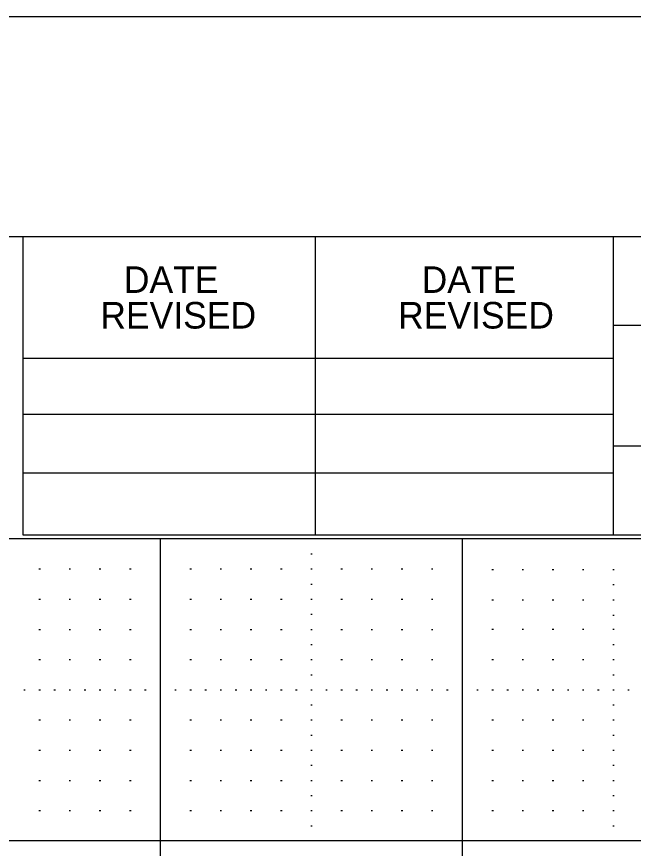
# Model space of a CAD drawing. Extents: x 0 to 34, y 0 to 22.
# Drawn here: x 26.93 to 28.972, y 19.247 to 22 of the extents above; entities that cross this region are included whole.
import ezdxf

# ---------------------------------------------------------------- set-up
doc = ezdxf.new("R2010")
doc.units = 0
for name, color, linetype in [('Level 1', 7, 'Continuous'), ('Level 4', 7, 'Continuous'), ('Level 5', 7, 'Continuous'), ('Level 63', 7, 'Continuous')]:
    doc.layers.add(name, color=color, linetype=linetype)

msp = doc.modelspace()

# ---------------------------------------------------------------- linework, layer by layer
at = {"layer": 'Level 1'}
for p, q in [((1.597, 21.272), (33.215, 21.272)), ((26.951, 20.2839), (26.951, 21.2719)), ((27.919, 20.2839), (27.919, 21.272)), ((28.905, 21.2719), (28.905, 20.2839)), ((33.215, 20.9779), (28.905, 20.9779)), ((26.951, 20.8699), (28.905, 20.8699)), ((26.951, 20.6839), (28.905, 20.6839)), ((33.215, 20.5779), (28.905, 20.5779)), ((26.951, 20.4899), (28.905, 20.4899)), ((33.215, 20.2839), (26.951, 20.2839))]:
    msp.add_line(p, q, dxfattribs=at)
at = {"layer": 'Level 4'}
for p, q in [((33.215, 20.272), (1.597, 20.272)), ((27.406, 1.272), (27.406, 20.272)), ((28.406, 1.272), (28.406, 20.272)), ((33.215, 19.272), (1.597, 19.272))]:
    msp.add_line(p, q, dxfattribs=at)
at = {"layer": 'Level 5'}
for p, q in [((27.9035, 20.2219), (27.9085, 20.2219)), ((27.0035, 20.1719), (27.0085, 20.1719)), ((27.1035, 20.1719), (27.1085, 20.1719)), ((27.2035, 20.1719), (27.2085, 20.1719)), ((27.3035, 20.1719), (27.3085, 20.1719)), ((27.5035, 20.1719), (27.5085, 20.1719)), ((27.6035, 20.1719), (27.6085, 20.1719)), ((27.7035, 20.1719), (27.7085, 20.1719)), ((27.8035, 20.1719), (27.8085, 20.1719)), ((27.9035, 20.1719), (27.9085, 20.1719)), ((28.0035, 20.1719), (28.0085, 20.1719)), ((28.1035, 20.1719), (28.1085, 20.1719)), ((28.2035, 20.1719), (28.2085, 20.1719)), ((28.3035, 20.1719), (28.3085, 20.1719)), ((28.5035, 20.1705), (28.5085, 20.1705)), ((28.6035, 20.1705), (28.6085, 20.1705)), ((28.7035, 20.1705), (28.7085, 20.1705)), ((28.8035, 20.1705), (28.8085, 20.1705)), ((28.9035, 20.1705), (28.9085, 20.1705)), ((27.9035, 20.1219), (27.9085, 20.1219)), ((28.9035, 20.1205), (28.9085, 20.1205)), ((27.0035, 20.0719), (27.0085, 20.0719)), ((27.1035, 20.0719), (27.1085, 20.0719)), ((27.2035, 20.0719), (27.2085, 20.0719)), ((27.3035, 20.0719), (27.3085, 20.0719)), ((27.5035, 20.0719), (27.5085, 20.0719)), ((27.6035, 20.0719), (27.6085, 20.0719)), ((27.7035, 20.0719), (27.7085, 20.0719)), ((27.8035, 20.0719), (27.8085, 20.0719)), ((27.9035, 20.0719), (27.9085, 20.0719)), ((28.0035, 20.0719), (28.0085, 20.0719)), ((28.1035, 20.0719), (28.1085, 20.0719)), ((28.2035, 20.0719), (28.2085, 20.0719)), ((28.3035, 20.0719), (28.3085, 20.0719)), ((28.5035, 20.0691), (28.5085, 20.0691)), ((28.6035, 20.0691), (28.6085, 20.0691)), ((28.7035, 20.0691), (28.7085, 20.0691)), ((28.8035, 20.0691), (28.8085, 20.0691)), ((28.9035, 20.0691), (28.9085, 20.0691)), ((27.9035, 20.0219), (27.9085, 20.0219)), ((28.9035, 20.0191), (28.9085, 20.0191)), ((27.0035, 19.9719), (27.0085, 19.9719)), ((27.1035, 19.9719), (27.1085, 19.9719)), ((27.2035, 19.9719), (27.2085, 19.9719)), ((27.3035, 19.9719), (27.3085, 19.9719)), ((27.5035, 19.9719), (27.5085, 19.9719)), ((27.6035, 19.9719), (27.6085, 19.9719)), ((27.7035, 19.9719), (27.7085, 19.9719)), ((27.8035, 19.9719), (27.8085, 19.9719)), ((27.9035, 19.9719), (27.9085, 19.9719)), ((28.0035, 19.9719), (28.0085, 19.9719)), ((28.1035, 19.9719), (28.1085, 19.9719)), ((28.2035, 19.9719), (28.2085, 19.9719)), ((28.3035, 19.9719), (28.3085, 19.9719)), ((28.5035, 19.9722), (28.5085, 19.9722)), ((28.6035, 19.9722), (28.6085, 19.9722)), ((28.7035, 19.9722), (28.7085, 19.9722)), ((28.8035, 19.9722), (28.8085, 19.9722)), ((28.9035, 19.9722), (28.9085, 19.9722)), ((27.9035, 19.9219), (27.9085, 19.9219)), ((28.9035, 19.9222), (28.9085, 19.9222)), ((27.0035, 19.8719), (27.0085, 19.8719)), ((27.1035, 19.8719), (27.1085, 19.8719)), ((27.2035, 19.8719), (27.2085, 19.8719)), ((27.3035, 19.8719), (27.3085, 19.8719)), ((27.5035, 19.8719), (27.5085, 19.8719)), ((27.6035, 19.8719), (27.6085, 19.8719)), ((27.7035, 19.8719), (27.7085, 19.8719)), ((27.8035, 19.8719), (27.8085, 19.8719)), ((27.9035, 19.8719), (27.9085, 19.8719)), ((28.0035, 19.8719), (28.0085, 19.8719)), ((28.1035, 19.8719), (28.1085, 19.8719)), ((28.2035, 19.8719), (28.2085, 19.8719)), ((28.3035, 19.8719), (28.3085, 19.8719)), ((28.5035, 19.8719), (28.5085, 19.8719)), ((28.6035, 19.8719), (28.6085, 19.8719)), ((28.7035, 19.8719), (28.7085, 19.8719)), ((28.8035, 19.8719), (28.8085, 19.8719)), ((28.9035, 19.8719), (28.9085, 19.8719)), ((27.9035, 19.8219), (27.9085, 19.8219)), ((28.9035, 19.8219), (28.9085, 19.8219)), ((26.9535, 19.7719), (26.9585, 19.7719)), ((27.0035, 19.7719), (27.0085, 19.7719)), ((27.0535, 19.7719), (27.0585, 19.7719)), ((27.1035, 19.7719), (27.1085, 19.7719)), ((27.1535, 19.7719), (27.1585, 19.7719)), ((27.2035, 19.7719), (27.2085, 19.7719)), ((27.2535, 19.7719), (27.2585, 19.7719)), ((27.3035, 19.7719), (27.3085, 19.7719)), ((27.3535, 19.7719), (27.3585, 19.7719)), ((27.4535, 19.7719), (27.4585, 19.7719)), ((27.5035, 19.7719), (27.5085, 19.7719)), ((27.5535, 19.7719), (27.5585, 19.7719)), ((27.6035, 19.7719), (27.6085, 19.7719)), ((27.6535, 19.7719), (27.6585, 19.7719)), ((27.7035, 19.7719), (27.7085, 19.7719)), ((27.7535, 19.7719), (27.7585, 19.7719)), ((27.8035, 19.7719), (27.8085, 19.7719)), ((27.8535, 19.7719), (27.8585, 19.7719)), ((27.9035, 19.7719), (27.9085, 19.7719)), ((27.9535, 19.7719), (27.9585, 19.7719)), ((28.0035, 19.7719), (28.0085, 19.7719)), ((28.0535, 19.7719), (28.0585, 19.7719)), ((28.1035, 19.7719), (28.1085, 19.7719)), ((28.1535, 19.7719), (28.1585, 19.7719)), ((28.2035, 19.7719), (28.2085, 19.7719)), ((28.2535, 19.7719), (28.2585, 19.7719)), ((28.3035, 19.7719), (28.3085, 19.7719)), ((28.3535, 19.7719), (28.3585, 19.7719)), ((28.4535, 19.7719), (28.4585, 19.7719)), ((28.5035, 19.7719), (28.5085, 19.7719)), ((28.5535, 19.7719), (28.5585, 19.7719)), ((28.6035, 19.7719), (28.6085, 19.7719)), ((28.6535, 19.7719), (28.6585, 19.7719)), ((28.7035, 19.7719), (28.7085, 19.7719)), ((28.7535, 19.7719), (28.7585, 19.7719)), ((28.8035, 19.7719), (28.8085, 19.7719)), ((28.8535, 19.7719), (28.8585, 19.7719)), ((28.9035, 19.7719), (28.9085, 19.7719)), ((28.9535, 19.7719), (28.9585, 19.7719)), ((27.9035, 19.7219), (27.9085, 19.7219)), ((28.9035, 19.7219), (28.9085, 19.7219)), ((27.0035, 19.6719), (27.0085, 19.6719)), ((27.1035, 19.6719), (27.1085, 19.6719)), ((27.2035, 19.6719), (27.2085, 19.6719)), ((27.3035, 19.6719), (27.3085, 19.6719)), ((27.5035, 19.6719), (27.5085, 19.6719)), ((27.6035, 19.6719), (27.6085, 19.6719)), ((27.7035, 19.6719), (27.7085, 19.6719)), ((27.8035, 19.6719), (27.8085, 19.6719)), ((27.9035, 19.6719), (27.9085, 19.6719)), ((28.0035, 19.6719), (28.0085, 19.6719)), ((28.1035, 19.6719), (28.1085, 19.6719)), ((28.2035, 19.6719), (28.2085, 19.6719)), ((28.3035, 19.6719), (28.3085, 19.6719)), ((28.5035, 19.6719), (28.5085, 19.6719)), ((28.6035, 19.6719), (28.6085, 19.6719)), ((28.7035, 19.6719), (28.7085, 19.6719)), ((28.8035, 19.6719), (28.8085, 19.6719)), ((28.9035, 19.6719), (28.9085, 19.6719)), ((27.9035, 19.6219), (27.9085, 19.6219)), ((28.9035, 19.6219), (28.9085, 19.6219)), ((27.0035, 19.5719), (27.0085, 19.5719)), ((27.1035, 19.5719), (27.1085, 19.5719)), ((27.2035, 19.5719), (27.2085, 19.5719)), ((27.3035, 19.5719), (27.3085, 19.5719)), ((27.5035, 19.5719), (27.5085, 19.5719)), ((27.6035, 19.5719), (27.6085, 19.5719)), ((27.7035, 19.5719), (27.7085, 19.5719)), ((27.8035, 19.5719), (27.8085, 19.5719)), ((27.9035, 19.5719), (27.9085, 19.5719)), ((28.0035, 19.5719), (28.0085, 19.5719)), ((28.1035, 19.5719), (28.1085, 19.5719)), ((28.2035, 19.5719), (28.2085, 19.5719)), ((28.3035, 19.5719), (28.3085, 19.5719)), ((28.5035, 19.5719), (28.5085, 19.5719)), ((28.6035, 19.5719), (28.6085, 19.5719)), ((28.7035, 19.5719), (28.7085, 19.5719)), ((28.8035, 19.5719), (28.8085, 19.5719)), ((28.9035, 19.5719), (28.9085, 19.5719)), ((27.9035, 19.5219), (27.9085, 19.5219)), ((28.9035, 19.5219), (28.9085, 19.5219)), ((27.0035, 19.4719), (27.0085, 19.4719)), ((27.1035, 19.4719), (27.1085, 19.4719)), ((27.2035, 19.4719), (27.2085, 19.4719)), ((27.3035, 19.4719), (27.3085, 19.4719)), ((27.5035, 19.4719), (27.5085, 19.4719)), ((27.6035, 19.4719), (27.6085, 19.4719)), ((27.7035, 19.4719), (27.7085, 19.4719)), ((27.8035, 19.4719), (27.8085, 19.4719)), ((27.9035, 19.4719), (27.9085, 19.4719)), ((28.0035, 19.4719), (28.0085, 19.4719)), ((28.1035, 19.4719), (28.1085, 19.4719)), ((28.2035, 19.4719), (28.2085, 19.4719)), ((28.3035, 19.4719), (28.3085, 19.4719)), ((28.5035, 19.4719), (28.5085, 19.4719)), ((28.6035, 19.4719), (28.6085, 19.4719)), ((28.7035, 19.4719), (28.7085, 19.4719)), ((28.8035, 19.4719), (28.8085, 19.4719)), ((28.9035, 19.4719), (28.9085, 19.4719)), ((27.9035, 19.4219), (27.9085, 19.4219)), ((28.9035, 19.4219), (28.9085, 19.4219)), ((27.0035, 19.3719), (27.0085, 19.3719)), ((27.1035, 19.3719), (27.1085, 19.3719)), ((27.2035, 19.3719), (27.2085, 19.3719)), ((27.3035, 19.3719), (27.3085, 19.3719)), ((27.5035, 19.3719), (27.5085, 19.3719)), ((27.6035, 19.3719), (27.6085, 19.3719)), ((27.7035, 19.3719), (27.7085, 19.3719)), ((27.8035, 19.3719), (27.8085, 19.3719)), ((27.9035, 19.3719), (27.9085, 19.3719)), ((28.0035, 19.3719), (28.0085, 19.3719)), ((28.1035, 19.3719), (28.1085, 19.3719)), ((28.2035, 19.3719), (28.2085, 19.3719)), ((28.3035, 19.3719), (28.3085, 19.3719)), ((28.5035, 19.3719), (28.5085, 19.3719)), ((28.6035, 19.3719), (28.6085, 19.3719)), ((28.7035, 19.3719), (28.7085, 19.3719)), ((28.8035, 19.3719), (28.8085, 19.3719)), ((28.9035, 19.3719), (28.9085, 19.3719)), ((27.9035, 19.3219), (27.9085, 19.3219)), ((28.9035, 19.3219), (28.9085, 19.3219))]:
    msp.add_line(p, q, dxfattribs=at)
at = {"layer": 'Level 63'}
msp.add_lwpolyline([(0, 22), (34, 22), (34, 0), (0, 0)], close=True, dxfattribs=at)

# ---------------------------------------------------------------- texts
at = {"layer": 'Level 1'}
for s, p in [('DATE', (27.2848, 21.0856)), ('DATE', (28.2708, 21.0856)), ('REVISED', (27.2068, 20.9676)), ('REVISED', (28.1928, 20.9676))]:
    msp.add_text(s, height=0.08792, dxfattribs=at).set_placement(p)

doc.saveas('drawing.dxf')
